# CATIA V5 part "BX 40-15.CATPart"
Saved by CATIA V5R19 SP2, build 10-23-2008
Part number: BX 40-15
Bounding box of the stored display mesh (mm): x -12.497 to 12.497, y -12.358 to 12.358, z 0 to 90
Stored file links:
  C:\Users\Bora\Desktop\3D Katı model\BX serisi\BX 40\BX 40-10\BX 40-15.CATPart
  C:\Program Files\Dassault Systemes\B19\intel_a\reffiles\standard\MetricThickPitch.txt
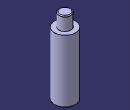
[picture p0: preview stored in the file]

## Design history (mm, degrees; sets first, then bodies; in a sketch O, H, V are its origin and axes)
Body1 (main body)
  Sketch1 on yz-plane, origin (0, 0, 0), H (0, 1, 0), V (0, 0, 1)
    point P3 (7, 89)
    point P5 (7, 89)
    line L1 (12.5, 74) -> (12.5, 0)
    line L2 (7, 89) -> (7, 74)
    arc A1 centre (6, 89) radius 1 from (7, 89) to (6, 90) ccw
    line L3 (6, 90) -> (0, 90)
    point P7 (0, 90)
    line L4 (7, 74) -> (12.5, 74)
    line L5 (12.5, 0) -> (0, 0)
    coincidence: P7 V, P5 P3
    tangency: L3 A1
    horizontal: L4 H, L5 H
  Shaft1: profile Sketch1, axis Sketch1.V, angle 360
  Plane1 to Plane3: linked copy from another document
  Sketch2 on face of Shaft1 from Sketch1.L5, origin (0, 0, 0), H (1, 0, 0), V (0, -1, 0)
    point P1 (6, 0)
    distance P1 V = 6
  Hole1: placed by Sketch2, at (6, 0, 0) direction (0, 0, 1), diameter 3.242, depth 5, threaded "M4", thread diameter 4, thread depth 5, pitch 0.7
  Sketch3 on face of Shaft1 from Sketch1.L5, origin (0, 0, 0), H (1, 0, 0), V (0, -1, 0)
    point P1 (-6, 0)
    distance P1 V = 6
    distance P1 H = 0
  Hole2: placed by Sketch3, at (-6, 0, 0) direction (0, 0, 1), diameter 3.242, depth 5, threaded "M4", thread diameter 4, thread depth 5, pitch 0.7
